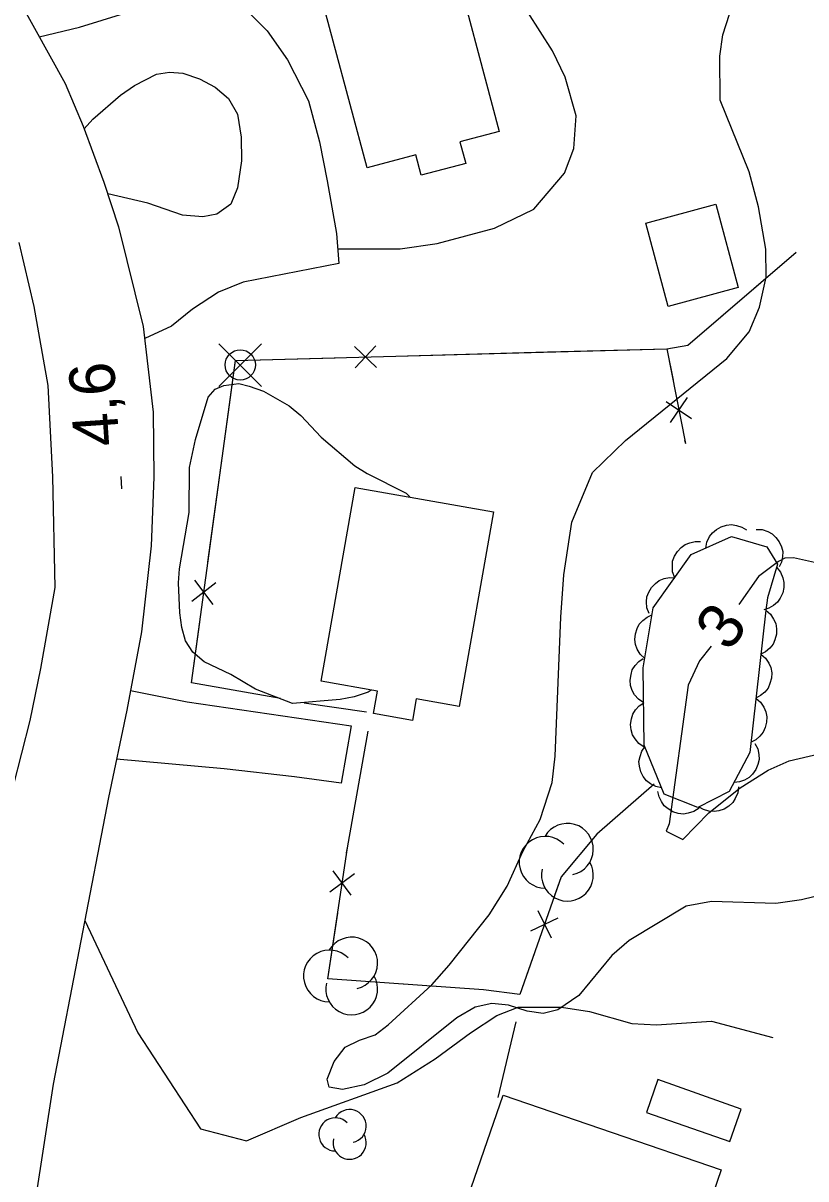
# Model space of a CAD drawing. Extents: x 282461 to 284471, y 5554090 to 5557646.
# Drawn here: x 283274.2 to 283325.8, y 5555349.2 to 5555425.4 of the extents above; entities that cross this region are included whole.
import ezdxf

# ---------------------------------------------------------------- set-up
doc = ezdxf.new("R2010")
doc.units = 0
for name, color, linetype in [('Niveau 1', 7, 'Continuous'), ('Niveau 19', 7, 'Continuous'), ('Niveau 2', 7, 'Continuous'), ('Niveau 21', 7, 'Continuous'), ('Niveau 22', 7, 'Continuous'), ('Niveau 3', 7, 'Continuous'), ('Niveau 31', 7, 'Continuous'), ('Niveau 36', 7, 'Continuous'), ('Niveau 37', 7, 'Continuous'), ('Niveau 44', 7, 'Continuous')]:
    doc.layers.add(name, color=color, linetype=linetype)

msp = doc.modelspace()

# ---------------------------------------------------------------- linework, layer by layer
at = {"layer": 'Niveau 1'}
for points in [[(283291.93, 5555380.54), (283289.48, 5555381.5), (283287.85, 5555382.46), (283286.1, 5555383.31), (283285.34, 5555383.94), (283284.86, 5555384.69), (283284.62, 5555385.56), (283284.49, 5555386.54), (283284.41, 5555388.51), (283284.46, 5555389.44), (283285.11, 5555393.16), (283285.13, 5555396.11), (283285.52, 5555397.97), (283286.35, 5555400.76), (283286.81, 5555401.29), (283287.39, 5555401.53), (283288.37, 5555401.65), (283289.07, 5555401.49), (283290, 5555401.15), (283291.7, 5555400.18), (283292.46, 5555399.56), (283293.81, 5555398.12), (283296.04, 5555396.23), (283296.85, 5555395.72), (283299.42, 5555394.42), (283299.65, 5555394.19)], [(283297.1, 5555381.42), (283296.91, 5555381.29), (283295.99, 5555380.99), (283295.06, 5555380.81), (283291.93, 5555380.54)]]:
    msp.add_lwpolyline(points, dxfattribs=at)
at = {"layer": 'Niveau 19'}
for points in [[(283275.22, 5555424.53), (283277.87, 5555425.17), (283280.87, 5555426.09), (283284.5, 5555426.96), (283285.89, 5555427.15), (283287.28, 5555427.06), (283288.78, 5555426.4), (283290.24, 5555424.92), (283291.6, 5555423.02), (283292.97, 5555420.31), (283293.69, 5555417.6), (283294.2, 5555415.04), (283294.83, 5555411.55), (283294.97, 5555409.58), (283288.66, 5555408.35), (283287.04, 5555407.69), (283285.32, 5555406.57), (283283.94, 5555405.45), (283282.18, 5555404.62)], [(283278.17, 5555418.47), (283278.75, 5555419.1), (283280.58, 5555420.69), (283281.51, 5555421.33), (283282.94, 5555422.06), (283283.81, 5555422.19), (283284.68, 5555422.14), (283285.78, 5555421.76), (283286.82, 5555421.21), (283287.7, 5555420.46), (283288.29, 5555419.43), (283288.54, 5555417.92), (283288.56, 5555416.36), (283288.29, 5555414.56), (283287.85, 5555413.49), (283286.93, 5555412.84), (283286, 5555412.66), (283284.67, 5555412.76), (283282.39, 5555413.55), (283279.74, 5555414.17)], [(283281.24, 5555381.41), (283284.98, 5555380.66), (283295.78, 5555379.07), (283295.13, 5555375.29), (283292.05, 5555375.72), (283287.41, 5555376.23), (283280.31, 5555376.87)]]:
    msp.add_lwpolyline(points, dxfattribs=at)
at = {"layer": 'Niveau 2'}
for points in [[(283308.44, 5555360.1), (283307.39, 5555360.26), (283306.17, 5555360.66), (283305.06, 5555360.76), (283303.96, 5555360.52), (283302.75, 5555359.81), (283298.21, 5555356.16), (283296.65, 5555355.39), (283295.21, 5555355.08), (283294.33, 5555355.25), (283294.21, 5555355.77), (283294.66, 5555356.93), (283295.4, 5555357.87), (283296.33, 5555358.34), (283297.37, 5555358.7), (283298.23, 5555359.35), (283301.1, 5555361.99), (283302.25, 5555363.28), (283304.88, 5555366.62), (283306.08, 5555368.49), (283307.12, 5555370.79), (283308.26, 5555372.89), (283309.04, 5555375.34), (283309.25, 5555377.08), (283309.61, 5555386.25), (283309.81, 5555389.03), (283310.35, 5555392.52), (283311.7, 5555395.79), (283313.88, 5555397.9), (283320.56, 5555403.31), (283322.04, 5555405.07), (283322.72, 5555406.7), (283323.16, 5555408.68), (283323.14, 5555410.53), (283322.64, 5555413.31), (283322.04, 5555415.63), (283320.12, 5555420.36), (283320.09, 5555423.26), (283320.3, 5555424.66), (283321.42, 5555428.15)], [(283326.34, 5555389.85), (283324.95, 5555390.17), (283324.38, 5555390.14), (283323.96, 5555389.91), (283322.65, 5555388.92), (283321.36, 5555387.08)], [(283319.53, 5555384.33), (283318.76, 5555383.36), (283318.01, 5555381.77), (283316.75, 5555372.62), (283316.56, 5555372.13), (283317.65, 5555371.57), (283319.38, 5555373.33), (283321.45, 5555374.98), (283323.29, 5555376.16), (283324.68, 5555376.76), (283326.65, 5555377.24)], [(283329.01, 5555368.45), (283325.48, 5555367.6), (283323.8, 5555367.35), (283319.56, 5555367.48), (283317.88, 5555367.17), (283314.13, 5555364.92), (283312.98, 5555363.92), (283310.81, 5555361.29), (283309.42, 5555360.34), (283308.44, 5555360.1)]]:
    msp.add_lwpolyline(points, dxfattribs=at)
at = {"layer": 'Niveau 21'}
for points in [[(283273.9, 5555426.92), (283276.92, 5555421.46), (283278.11, 5555418.63), (283279.48, 5555414.95), (283280.45, 5555412), (283282.08, 5555405.43), (283282.72, 5555399.77), (283282.77, 5555395.48), (283282.6, 5555390.96), (283281.97, 5555385.27), (283280.99, 5555380.1), (283279.78, 5555374.35), (283276.13, 5555355.43), (283273.72, 5555339.76)], [(283273.51, 5555375.13), (283274.62, 5555379.43), (283275.33, 5555382.86), (283276.26, 5555388.2), (283276.11, 5555395.5), (283275.81, 5555401.53), (283274.88, 5555406.74), (283273.9, 5555410.96)]]:
    msp.add_lwpolyline(points, dxfattribs=at)
at = {"layer": 'Niveau 22'}
for points in [[(283294.9, 5555410.54), (283299.03, 5555410.54), (283301.47, 5555410.9), (283305.24, 5555411.91), (283307.84, 5555413.16), (283309.85, 5555415.54), (283310.47, 5555417.17), (283310.62, 5555419.32), (283309.9, 5555421.87), (283309.06, 5555423.6), (283305.81, 5555428.72)], [(283278.23, 5555366.24), (283281.71, 5555358.82), (283285.85, 5555352.49), (283288.88, 5555351.71), (283292.46, 5555353.25), (283298.82, 5555355.53), (283301.33, 5555357.11), (283303.65, 5555358.83), (283305.4, 5555359.97), (283306.81, 5555360.52), (283309.67, 5555360.52), (283311.51, 5555360.23), (283314.3, 5555359.45), (283315.93, 5555359.36), (283319.55, 5555359.59), (283323.6, 5555358.51)]]:
    msp.add_lwpolyline(points, dxfattribs=at)
at = {"layer": 'Niveau 3'}
msp.add_line((283280.67, 5555394.72), (283280.61, 5555395.52), dxfattribs=at)
at = {"layer": 'Niveau 31'}
for points in [[(283302.24, 5555430.79), (283305.55, 5555418.29), (283302.96, 5555417.6), (283303.34, 5555416.18), (283300.4, 5555415.4), (283300.05, 5555416.74), (283296.84, 5555415.88), (283293.48, 5555428.44), (283302.24, 5555430.79)], [(283315.21, 5555412.24), (283319.83, 5555413.49), (283321.32, 5555407.99), (283316.7, 5555406.74), (283315.21, 5555412.24)], [(283305.17, 5555393.19), (283302.9, 5555380.35), (283300.08, 5555380.85), (283299.83, 5555379.44), (283297.27, 5555379.89), (283297.53, 5555381.36), (283293.8, 5555382.02), (283296.06, 5555394.8), (283305.17, 5555393.19)], [(283320.76, 5555351.65), (283321.51, 5555353.8), (283316.02, 5555355.74), (283315.26, 5555353.58), (283320.76, 5555351.65)], [(283305.81, 5555354.72), (283320.19, 5555349.79), (283317.48, 5555341.89), (283303.09, 5555346.82), (283305.81, 5555354.72)]]:
    msp.add_lwpolyline(points, dxfattribs=at)
at = {"layer": 'Niveau 36'}
for p, q in [((283289.88, 5555401.46), (283287.06, 5555404.28)), ((283287.06, 5555401.46), (283289.88, 5555404.28))]:
    msp.add_line(p, q, dxfattribs=at)
msp.add_circle((283288.474, 5555402.885), 1, dxfattribs=at)
at = {"layer": 'Niveau 37'}
for p, q in [((283297.46, 5555402.72), (283296.01, 5555404.1)), ((283296.05, 5555402.69), (283297.42, 5555404.14)), ((283316.84, 5555399.08), (283317.96, 5555400.74)), ((283316.57, 5555400.47), (283318.23, 5555399.35)), ((283286.87, 5555388.5), (283285.27, 5555387.29)), ((283286.68, 5555387.09), (283285.47, 5555388.69)), ((283296, 5555369.31), (283294.39, 5555368.11)), ((283295.79, 5555367.91), (283294.6, 5555369.51)), ((283307.63, 5555365.55), (283309.43, 5555366.42)), ((283308.1, 5555366.89), (283308.97, 5555365.09))]:
    msp.add_line(p, q, dxfattribs=at)
for points in [[(283316.61, 5555403.95), (283318, 5555404.2), (283325.14, 5555410.33)], [(283316.61, 5555403.95), (283318, 5555404.2), (283324.52, 5555409.79)], [(283291.12, 5555380.87), (283285.25, 5555381.91), (283288.17, 5555403.18), (283316.61, 5555403.95), (283317.83, 5555397.7)], [(283298.74, 5555403.47), (283308.73, 5555403.74)], [(283308.73, 5555403.74), (283316.61, 5555403.95), (283317.02, 5555401.87)], [(283287.7, 5555399.78), (283288.17, 5555403.18), (283294.74, 5555403.36)], [(283286.34, 5555389.87), (283287.7, 5555399.78)], [(283317.78, 5555397.94), (283317.83, 5555397.7)], [(283291.12, 5555380.87), (283285.25, 5555381.91), (283285.8, 5555385.91)], [(283292.69, 5555380.6), (283296.81, 5555380.01)], [(283292.69, 5555380.6), (283296.81, 5555380.01)], [(283315.77, 5555375.22), (283311.98, 5555371.93), (283309.63, 5555369.12), (283306.91, 5555361.36), (283304.51, 5555361.67), (283294.25, 5555362.39), (283295.54, 5555371.04), (283296.92, 5555378.72)], [(283295.49, 5555370.69), (283295.54, 5555371.04), (283296.92, 5555378.72)], [(283315.77, 5555375.22), (283311.98, 5555371.93), (283309.63, 5555369.12), (283309.19, 5555367.88)], [(283299.85, 5555362), (283294.25, 5555362.39), (283294.9, 5555366.73)], [(283307.87, 5555364.1), (283306.91, 5555361.36), (283304.51, 5555361.67), (283299.85, 5555362)], [(283306.65, 5555359.56), (283305.46, 5555354.55)], [(283306.65, 5555359.56), (283305.46, 5555354.55)]]:
    msp.add_lwpolyline(points, dxfattribs=at)
at = {"layer": 'Niveau 44'}
for points in [[(283319.18, 5555390.8), (283319.25, 5555391.2), (283319.43, 5555391.56), (283319.61, 5555391.82), (283319.88, 5555392.04), (283320.19, 5555392.21), (283320.55, 5555392.31), (283320.87, 5555392.35), (283321.21, 5555392.3), (283321.55, 5555392.18), (283321.85, 5555392)], [(283323.13, 5555386.71), (283322.08, 5555377.31), (283320.72, 5555374.74), (283318.65, 5555373.68), (283316.43, 5555374.58), (283315.11, 5555377.81), (283315.05, 5555382.91), (283315.7, 5555386.86), (283318.22, 5555390.37), (283320.87, 5555391.56), (283323.2, 5555390.89), (283323.91, 5555389.74), (283323.24, 5555387.53), (283323.13, 5555386.71)], [(283322.49, 5555392.04), (283322.89, 5555392.03), (283323.27, 5555391.89), (283323.56, 5555391.75), (283323.8, 5555391.51), (283324.02, 5555391.22), (283324.16, 5555390.88), (283324.25, 5555390.57), (283324.24, 5555390.23), (283324.17, 5555389.88), (283324.02, 5555389.56)], [(283317.13, 5555388.85), (283316.99, 5555389.23), (283316.97, 5555389.63), (283316.99, 5555389.95), (283317.11, 5555390.27), (283317.3, 5555390.58), (283317.56, 5555390.84), (283317.81, 5555391.04), (283318.13, 5555391.16), (283318.48, 5555391.24), (283318.83, 5555391.23)], [(283323.85, 5555389.53), (283324.1, 5555389.22), (283324.25, 5555388.85), (283324.33, 5555388.54), (283324.32, 5555388.2), (283324.25, 5555387.85), (283324.08, 5555387.51), (283323.91, 5555387.24), (283323.65, 5555387.02), (283323.33, 5555386.84), (283323, 5555386.74)], [(283315.43, 5555386.48), (283315.29, 5555386.86), (283315.26, 5555387.26), (283315.29, 5555387.58), (283315.41, 5555387.9), (283315.59, 5555388.21), (283315.86, 5555388.47), (283316.11, 5555388.67), (283316.43, 5555388.79), (283316.78, 5555388.86), (283317.13, 5555388.85)], [(283315.15, 5555383.52), (283314.85, 5555383.8), (283314.66, 5555384.14), (283314.54, 5555384.44), (283314.5, 5555384.78), (283314.53, 5555385.14), (283314.65, 5555385.49), (283314.79, 5555385.78), (283315.02, 5555386.03), (283315.31, 5555386.25), (283315.62, 5555386.4)], [(283323.13, 5555386.71), (283323.44, 5555386.45), (283323.65, 5555386.11), (283323.79, 5555385.82), (283323.84, 5555385.48), (283323.83, 5555385.12), (283323.73, 5555384.76), (283323.61, 5555384.47), (283323.39, 5555384.21), (283323.12, 5555383.97), (283322.81, 5555383.81)], [(283322.81, 5555383.81), (283323.12, 5555383.54), (283323.33, 5555383.21), (283323.46, 5555382.92), (283323.52, 5555382.58), (283323.51, 5555382.22), (283323.4, 5555381.86), (283323.28, 5555381.57), (283323.06, 5555381.3), (283322.79, 5555381.07), (283322.48, 5555380.9)], [(283315.08, 5555380.6), (283314.74, 5555380.83), (283314.48, 5555381.13), (283314.31, 5555381.4), (283314.22, 5555381.73), (283314.19, 5555382.09), (283314.25, 5555382.46), (283314.33, 5555382.77), (283314.51, 5555383.06), (283314.75, 5555383.32), (283315.04, 5555383.52)], [(283322.48, 5555380.9), (283322.79, 5555380.64), (283323, 5555380.31), (283323.14, 5555380.01), (283323.19, 5555379.68), (283323.18, 5555379.32), (283323.08, 5555378.96), (283322.96, 5555378.66), (283322.74, 5555378.4), (283322.47, 5555378.16), (283322.16, 5555378)], [(283315.11, 5555377.68), (283314.77, 5555377.91), (283314.52, 5555378.21), (283314.35, 5555378.48), (283314.26, 5555378.81), (283314.22, 5555379.17), (283314.28, 5555379.54), (283314.36, 5555379.85), (283314.55, 5555380.14), (283314.79, 5555380.4), (283315.08, 5555380.6)], [(283316.26, 5555374.99), (283315.87, 5555375.07), (283315.52, 5555375.26), (283315.26, 5555375.45), (283315.05, 5555375.73), (283314.89, 5555376.05), (283314.81, 5555376.41), (283314.77, 5555376.73), (283314.84, 5555377.06), (283314.96, 5555377.4), (283315.16, 5555377.69)], [(283322.4, 5555377.92), (283322.6, 5555377.57), (283322.67, 5555377.18), (283322.69, 5555376.86), (283322.61, 5555376.52), (283322.47, 5555376.19), (283322.25, 5555375.89), (283322.03, 5555375.66), (283321.73, 5555375.5), (283321.39, 5555375.38), (283321.04, 5555375.34)], [(283318.73, 5555373.65), (283318.39, 5555373.42), (283318.01, 5555373.31), (283317.7, 5555373.25), (283317.36, 5555373.3), (283317.01, 5555373.4), (283316.69, 5555373.6), (283316.44, 5555373.79), (283316.25, 5555374.08), (283316.1, 5555374.4), (283316.02, 5555374.75)], [(283321.33, 5555375.05), (283321.28, 5555374.65), (283321.12, 5555374.28), (283320.95, 5555374.01), (283320.69, 5555373.78), (283320.39, 5555373.59), (283320.03, 5555373.48), (283319.72, 5555373.42), (283319.38, 5555373.45), (283319.03, 5555373.55), (283318.73, 5555373.72)]]:
    msp.add_lwpolyline(points, dxfattribs=at)
for centre, radius, start, end in [((283310.049, 5555370.933), 1.708, 282.26917, 149.72625), ((283308.58, 5555370.079), 1.708, 44.11537, 269.80396), ((283310.049, 5555369.225), 1.708, 166.93686, 29.62122), ((283295.823, 5555363.429), 1.708, 282.26917, 149.72625), ((283294.354, 5555362.575), 1.708, 44.11537, 269.80396), ((283295.823, 5555361.721), 1.708, 166.93686, 29.62122), ((283295.688, 5555352.67), 1.093, 282.26917, 149.72625), ((283294.748, 5555352.124), 1.093, 44.11537, 269.80396), ((283295.688, 5555351.577), 1.093, 166.93686, 29.62122)]:
    msp.add_arc(centre, radius, start, end, dxfattribs=at)

# ---------------------------------------------------------------- texts
at = {"layer": 'Niveau 2'}
msp.add_text('3', height=3, rotation=53.73255, dxfattribs=at).set_placement((283320.7, 5555383.89))
at = {"layer": 'Niveau 3'}
msp.add_text('4,6  ', height=2.9999, rotation=93.88245, dxfattribs=at).set_placement((283280.51, 5555397.6))

doc.saveas('drawing.dxf')
